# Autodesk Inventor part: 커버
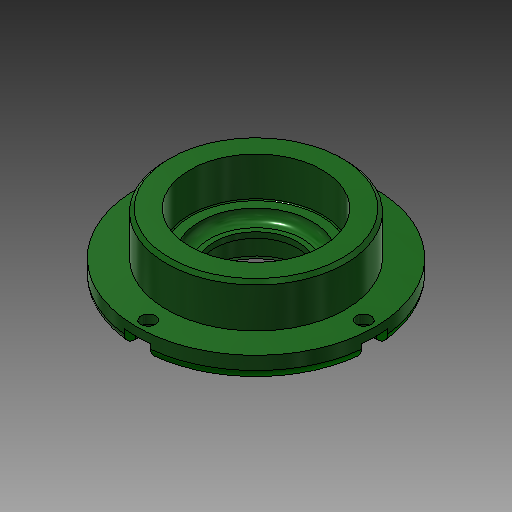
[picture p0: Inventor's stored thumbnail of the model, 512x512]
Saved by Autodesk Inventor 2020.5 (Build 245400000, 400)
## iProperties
Created: 2016-04
Part Number: 커버
Document SubType Name: Modeling
Designer: mdu
Density: 7.86 g/cm^3
Mass: 351.567 g
Surface Area: 161.165 cm^2
Volume: 44.7286 cm^3
Material: 강철, 연강
Appearance: 진녹색
Company: 한국ATC센터
Author: mdu
Revision Number: 1
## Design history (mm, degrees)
sketch "스케치1"
  geometry: C1 r 36 at (0, 0); 1 further point
  constraints: 1 centre point, 1 coincident
  dimensions: "d0" = 72 diameter of C1
extrude "돌출1" new body sketch "스케치1" distance "d1" = 7; taper "d2" = 0 deg
sketch "스케치2"
  geometry: C1 r 27 at (0, 0); 1 further point
  constraints: 1 centre point, 1 coincident
  dimensions: "d3" = 54 diameter of C1
extrude "돌출2" join sketch "스케치2" distance "d4" = 13; taper "d5" = 0 deg
sketch "스케치3"
  geometry: C1 r 20 at (0, 0); 1 further point
  constraints: 1 centre point, 1 coincident
  dimensions: "d6" = 40 diameter of C1
extrude "돌출3" join sketch "스케치3" distance "d7" = 5; taper "d8" = 0 deg
hole "구멍1" diameter "d11" = 25; stored, may be unused: countersink angle "d15" = 90 deg, drill point angle "d17" = 118 deg; dims "d9" = 10, "d10" = 10, "d12" = 6, "d13" = 32, "d14" = 8.3, "d16" = 8
hole "구멍2" diameter "d20" = 34; stored, may be unused: countersink angle "d24" = 90 deg, drill point angle "d26" = 0 deg; dims "d18" = 10, "d19" = 10, "d21" = 6, "d22" = 40, "d23" = 12, "d25" = 3
fillet "모깎기2" dims "d34" = 3
fillet "모깎기1" dims "d27" = 0.3
chamfer "모따기1" distance "d28" = 1; stored, may be unused: second distance "d29" = 2, angle "d30" = 45 deg
chamfer "모따기2" distance "d31" = 1.2; stored, may be unused: second distance "d32" = 2, angle "d33" = 30 deg
sketch "스케치4" dims "d35" = 65
  geometry: 3 further points
  constraints: 2 horizontal alignment, 1 coincident, 2 other
hole "구멍3" sketch "스케치4" at (32.5, 0) diameter "d36" = 4.5; stored, may be unused: countersink angle "d40" = 90 deg, drill point angle "d42" = 118 deg; dims "d37" = 6, "d38" = 8, "d39" = 4.4, "d41" = 13
sketch "스케치5"
  geometry: L1 (4, 0)-(4, 3.5); L2 (-4, 3.5)-(-4, 0); L3 (4, 3.5)-(-4, 3.5); C1 r 2.25 at (0, 0) reference; C2 r 36 at (0, -32.5) reference; A1 r 4 centre (0, 0) between (-2.037, 3.442) and (2.037, 3.442) reference; A2 r 36 centre (0, -32.5) between (2.037, 3.442) and (-2.037, 3.442) reference; 2 further points
  constraints: 6 end point, 2 horizontal alignment, 2 point on circle, 1 horizontal, 1 midpoint, 1 parallel, 1 tangent, 1 vertical, 1 vertical alignment
extrude "돌출4" cut sketch "스케치5" extent not by distance; stored distance "d47" = 24.5; taper "d48" = 0 deg
node "솔리드1"
pattern_circular "원형 패턴1" dims angle "d44" = 360 deg
pattern_circular "원형 패턴2" dims angle "d50" = 360 deg
node "투영된 루프1"
